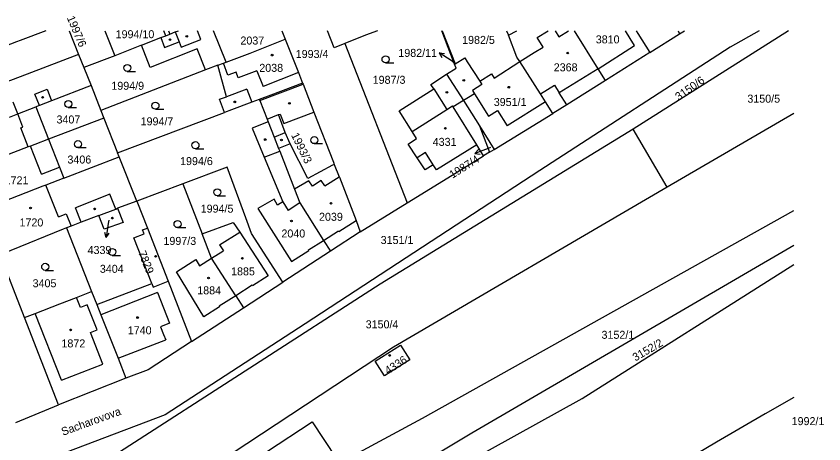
# Model space of a CAD drawing. Extents: x -564952 to -564307, y -1202373 to -1201847.
# Drawn here: x -564479.9 to -564308.3, y -1201937.9 to -1201847 of the extents above; entities that cross this region are included whole.
import ezdxf

# ---------------------------------------------------------------- set-up
doc = ezdxf.new("R2010")
doc.units = 0
for name, color, linetype in [('Hranice parcel', 7, 'Continuous'), ('Parcelní čísla', 7, 'Continuous'), ('Pop  PČ popisy', 7, 'Continuous'), ('Vnitřní kresba', 7, 'Continuous'), ('Značky budov', 7, 'Continuous'), ('Značky kultur', 7, 'Continuous')]:
    doc.layers.add(name, color=color, linetype=linetype)

msp = doc.modelspace()

# ---------------------------------------------------------------- linework, layer by layer
at = {"layer": 'Hranice parcel'}
for p, q in [((-564468.61, -1201850.07), (-564466.6, -1201855.11)), ((-564461.02, -1201850.07), (-564458.94, -1201855.38)), ((-564448.11, -1201851.13), (-564448.52, -1201850.07)), ((-564448.11, -1201851.13), (-564447.23, -1201850.78)), ((-564412.32, -1201853.69), (-564413.74, -1201850.07)), ((-564386.74, -1201857.21), (-564389.41, -1201850.07)), ((-564389.34, -1201850.07), (-564386.6, -1201857.12)), ((-564375.67, -1201850.07), (-564375.3, -1201851.01)), ((-564375.3, -1201851.01), (-564373.49, -1201850.07)), ((-564315.76, -1201850.07), (-564348.82, -1201871.01)), ((-564345.27, -1201854.72), (-564338.97, -1201850.76)), ((-564339.24, -1201850.07), (-564338.97, -1201850.76)), ((-564338.97, -1201850.76), (-564337.86, -1201850.07)), ((-564322.01, -1201850.07), (-564328.21, -1201853.59)), ((-564453.25, -1201853.14), (-564458.94, -1201855.38)), ((-564430.18, -1201854.86), (-564422.73, -1201851.85)), ((-564410.05, -1201852.79), (-564412.32, -1201853.69)), ((-564410.05, -1201852.79), (-564396.77, -1201886.65)), ((-564345.27, -1201854.72), (-564354.7, -1201860.63)), ((-564466.6, -1201855.11), (-564477.53, -1201859.28)), ((-564466.6, -1201855.11), (-564465.47, -1201857.93)), ((-564458.94, -1201855.38), (-564465.47, -1201857.93)), ((-564465.47, -1201857.93), (-564463.95, -1201861.74)), ((-564437.04, -1201857.43), (-564439.67, -1201858.41)), ((-564386.6, -1201857.12), (-564386.74, -1201857.21)), ((-564354.7, -1201860.63), (-564356.22, -1201858.17)), ((-564439.67, -1201858.41), (-564461.87, -1201867.04)), ((-564463.95, -1201861.74), (-564461.87, -1201867.04)), ((-564474.94, -1201865.99), (-564475.71, -1201866.29)), ((-564475.71, -1201866.29), (-564473.01, -1201873.15)), ((-564461.24, -1201868.64), (-564473.01, -1201873.15)), ((-564461.87, -1201867.04), (-564461.24, -1201868.64)), ((-564461.24, -1201868.64), (-564458.32, -1201876.01)), ((-564458.32, -1201876.01), (-564435.59, -1201867.46)), ((-564378.3, -1201875.31), (-564365.83, -1201867.67)), ((-564314.65, -1201867.64), (-564341.58, -1201883.31)), ((-564381.45, -1201870.33), (-564378.3, -1201875.31)), ((-564381.45, -1201870.33), (-564379.28, -1201875.91)), ((-564341.58, -1201883.31), (-564348.82, -1201871.01)), ((-564379.28, -1201875.91), (-564378.3, -1201875.31)), ((-564469.76, -1201881.43), (-564457.98, -1201876.88)), ((-564457.98, -1201876.88), (-564458.32, -1201876.01)), ((-564454.24, -1201886.28), (-564457.98, -1201876.88)), ((-564379.28, -1201875.91), (-564380.57, -1201876.7)), ((-564435.05, -1201879.07), (-564444.43, -1201882.6)), ((-564444.43, -1201882.6), (-564454.24, -1201886.28)), ((-564444.43, -1201882.6), (-564440.35, -1201893.28)), ((-564454.24, -1201886.28), (-564458.32, -1201887.83)), ((-564454.24, -1201886.28), (-564452, -1201892.04)), ((-564406.77, -1201892.86), (-564396.77, -1201886.65)), ((-564469.2, -1201891.98), (-564463.85, -1201905.51)), ((-564452, -1201892.04), (-564447.6, -1201903.34)), ((-564438.38, -1201898.44), (-564440.35, -1201893.28)), ((-564423.2, -1201903.54), (-564429.86, -1201893.15)), ((-564406.77, -1201892.86), (-564413.1, -1201896.97)), ((-564414.61, -1201894.66), (-564413.1, -1201896.97)), ((-564478.1, -1201911.04), (-564483.28, -1201897.71)), ((-564413.1, -1201896.97), (-564423.2, -1201903.54)), ((-564440.95, -1201900.03), (-564438.38, -1201898.44)), ((-564433.23, -1201906.4), (-564438.38, -1201898.44)), ((-564462.75, -1201908.3), (-564451.07, -1201903.8)), ((-564447.6, -1201903.34), (-564442.6, -1201916.17)), ((-564431.61, -1201909.01), (-564423.2, -1201903.54)), ((-564463.85, -1201905.51), (-564462.75, -1201908.3)), ((-564433.23, -1201906.4), (-564431.61, -1201909.01)), ((-564475.84, -1201910.17), (-564470.62, -1201908.16)), ((-564442.6, -1201916.17), (-564431.61, -1201909.01)), ((-564478.1, -1201911.04), (-564475.84, -1201910.17)), ((-564470.88, -1201929.59), (-564478.1, -1201911.04)), ((-564456.57, -1201923.91), (-564470.88, -1201929.59)), ((-564479.94, -1201933.37), (-564470.88, -1201929.59))]:
    msp.add_line(p, q, dxfattribs=at)
for points in [[(-564473.57, -1201850.07), (-564479.02, -1201852.16), (-564479.81, -1201852.47)], [(-564453.25, -1201853.14), (-564449.16, -1201851.54), (-564448.11, -1201851.13)], [(-564447.23, -1201850.78), (-564446.06, -1201850.33), (-564445.4, -1201850.07)], [(-564423.43, -1201850.07), (-564422.73, -1201851.85)], [(-564403.1, -1201850.07), (-564405.63, -1201851.04), (-564410.05, -1201852.79)], [(-564372.86, -1201856.63), (-564373.48, -1201855.67), (-564375.3, -1201851.01)], [(-564356.22, -1201858.17), (-564361.26, -1201850.07)], [(-564348.14, -1201850.07), (-564347.77, -1201850.67), (-564345.27, -1201854.72)], [(-564479.81, -1201852.47), (-564485.57, -1201854.67), (-564486.52, -1201855.04)], [(-564439.67, -1201858.41), (-564441.45, -1201853.96), (-564451.37, -1201857.87), (-564453.25, -1201853.14)], [(-564422.73, -1201851.85), (-564419.92, -1201858.94), (-564419.02, -1201861.22)], [(-564328.21, -1201853.59), (-564368.6, -1201879.82), (-564418.44, -1201912.36), (-564448.23, -1201931.71), (-564529.16, -1201962.4)], [(-564437.04, -1201857.43), (-564435.86, -1201856.99), (-564435.27, -1201856.77), (-564430.18, -1201854.86)], [(-564386.6, -1201857.12), (-564384.58, -1201855.83), (-564384.05, -1201856.66), (-564381.38, -1201860.81), (-564378.92, -1201859.23), (-564378.35, -1201860.13), (-564372.86, -1201856.63)], [(-564365.83, -1201867.67), (-564367.43, -1201865.16), (-564368.48, -1201863.51), (-564372.86, -1201856.63)], [(-564435.59, -1201867.46), (-564436.64, -1201864.66), (-564435.18, -1201864.11), (-564437.04, -1201857.43)], [(-564388.42, -1201859.31), (-564386.43, -1201858.04), (-564386.74, -1201857.21)], [(-564477.53, -1201859.28), (-564481.06, -1201860.63), (-564482.46, -1201861.16), (-564484.41, -1201861.91)], [(-564380.57, -1201876.7), (-564382.03, -1201874.33), (-564390.55, -1201879.66), (-564391.25, -1201878.56), (-564392.97, -1201879.66), (-564394.68, -1201877.07), (-564396.59, -1201874.17), (-564394.79, -1201872.98), (-564395.72, -1201871.52), (-564398.51, -1201867.12), (-564391.16, -1201862.46), (-564391.79, -1201861.48), (-564388.42, -1201859.31)], [(-564388.42, -1201859.31), (-564384.87, -1201864.93), (-564381.45, -1201870.33)], [(-564463.95, -1201861.74), (-564472.34, -1201864.98), (-564474.94, -1201865.99)], [(-564419.02, -1201861.22), (-564425.76, -1201863.76), (-564428.23, -1201864.69)], [(-564419.02, -1201861.22), (-564418.92, -1201861.47), (-564416.62, -1201867.36)], [(-564354.7, -1201860.63), (-564362.91, -1201865.83), (-564365.83, -1201867.67)], [(-564428.23, -1201864.69), (-564429.82, -1201865.29), (-564434.13, -1201866.91), (-564435.59, -1201867.46)], [(-564428.23, -1201864.69), (-564428.13, -1201864.92), (-564426.58, -1201868.88), (-564426.35, -1201869.45)], [(-564481.3, -1201868.45), (-564479.53, -1201867.76), (-564475.71, -1201866.29)], [(-564412.28, -1201878.49), (-564412.7, -1201878.65), (-564417.92, -1201881.46), (-564421.69, -1201874.11), (-564422.7, -1201871.73), (-564424.14, -1201867.92), (-564423.81, -1201867.79), (-564423.04, -1201869.79), (-564416.62, -1201867.36)], [(-564416.62, -1201867.36), (-564412.46, -1201878.03), (-564412.28, -1201878.49)], [(-564426.35, -1201869.45), (-564429.75, -1201870.82), (-564427.19, -1201876.93), (-564423.21, -1201886.47), (-564424.37, -1201887.16), (-564425.08, -1201885.85), (-564428.5, -1201887.89), (-564421.37, -1201899.14), (-564417.7, -1201896.81), (-564417.78, -1201896.68), (-564414.61, -1201894.66)], [(-564426.35, -1201869.45), (-564425.09, -1201872.67), (-564424.13, -1201875.09), (-564423.89, -1201875.7), (-564420.71, -1201883.77), (-564419.58, -1201886.65), (-564414.61, -1201894.66)], [(-564348.82, -1201871.01), (-564402.54, -1201903.93), (-564457.9, -1201939.66)], [(-564473.01, -1201873.15), (-564475.91, -1201874.26), (-564476.86, -1201874.62), (-564477.31, -1201874.79), (-564488.03, -1201878.9), (-564490.31, -1201879.77)], [(-564473.01, -1201873.15), (-564470.67, -1201879.1), (-564469.76, -1201881.43)], [(-564396.77, -1201886.65), (-564392.78, -1201884.18), (-564380.57, -1201876.7)], [(-564412.28, -1201878.49), (-564411.25, -1201881.16), (-564411.21, -1201881.24), (-564407.64, -1201890.41), (-564406.77, -1201892.86)], [(-564429.86, -1201893.15), (-564431.08, -1201889.83), (-564435.05, -1201879.07)], [(-564469.76, -1201881.43), (-564473.58, -1201882.9), (-564474.18, -1201883.13)], [(-564474.18, -1201883.13), (-564484.77, -1201887.21), (-564487.03, -1201888.15)], [(-564341.58, -1201883.31), (-564399.74, -1201917.34), (-564446.42, -1201948.18)], [(-564458.32, -1201887.83), (-564457.17, -1201890.85), (-564461.2, -1201892.28), (-564462.31, -1201889.35)], [(-564462.31, -1201889.35), (-564458.72, -1201887.98), (-564458.32, -1201887.83)], [(-564428.74, -1201951.43), (-564393.56, -1201932.42), (-564314.65, -1201888.26)], [(-564462.31, -1201889.35), (-564466.09, -1201890.79), (-564468.22, -1201891.6), (-564469.2, -1201891.98)], [(-564440.35, -1201893.28), (-564433.75, -1201890.82), (-564432.39, -1201892.9)], [(-564469.2, -1201891.98), (-564469.88, -1201892.25), (-564480.99, -1201896.78), (-564483.28, -1201897.71)], [(-564451.07, -1201903.8), (-564454.85, -1201894.08), (-564452.68, -1201893.23), (-564453, -1201892.42), (-564452, -1201892.04)], [(-564432.39, -1201892.9), (-564426.32, -1201902.19), (-564429.69, -1201904.33), (-564429.77, -1201904.2), (-564433.23, -1201906.4)], [(-564383.08, -1201935.53), (-564314.65, -1201895.68)], [(-564433.23, -1201906.4), (-564436.77, -1201908.65), (-564436.69, -1201908.77), (-564440.03, -1201910.89), (-564445.78, -1201901.35), (-564441.69, -1201898.72), (-564440.95, -1201900.03)], [(-564359.6, -1201928.27), (-564314.65, -1201899.76)], [(-564451.07, -1201903.8), (-564450.77, -1201904.57), (-564447.6, -1201903.34)], [(-564470.62, -1201908.16), (-564467.08, -1201906.76), (-564463.85, -1201905.51)], [(-564462.75, -1201908.3), (-564461.88, -1201910.49), (-564458.23, -1201919.71), (-564456.57, -1201923.91)], [(-564442.6, -1201916.17), (-564451.86, -1201922.16), (-564456.57, -1201923.91)], [(-564401.64, -1201923.47), (-564403.6, -1201920.35), (-564398.19, -1201916.95), (-564396.24, -1201920.07), (-564401.64, -1201923.47)], [(-564479.51, -1201991.57), (-564446.91, -1201976.65), (-564359.6, -1201928.27)], [(-564314.65, -1201928.08), (-564320.77, -1201931.52), (-564331.09, -1201937.56), (-564341.36, -1201943.65), (-564351.71, -1201949.82)], [(-564426.66, -1201939.6), (-564416.96, -1201933.2), (-564411.87, -1201940.91), (-564421.6, -1201947.33), (-564426.66, -1201939.6)], [(-564479.51, -1201991.57), (-564464.1, -1201982.45), (-564434.29, -1201966.3), (-564383.08, -1201935.53)]]:
    msp.add_lwpolyline(points, dxfattribs=at)
at = {"layer": 'Pop  PČ popisy'}
for p, q in [((-564387.49, -1201856.44), (-564390.01, -1201854.81)), ((-564390.01, -1201854.81), (-564388.89, -1201854.93)), ((-564390.01, -1201854.81), (-564389.44, -1201855.77)), ((-564386.81, -1201856.89), (-564387.49, -1201856.44)), ((-564379.62, -1201875.11), (-564382.42, -1201876.19)), ((-564382.42, -1201876.19), (-564381.67, -1201875.36)), ((-564379.07, -1201874.9), (-564379.62, -1201875.11)), ((-564382.42, -1201876.19), (-564381.31, -1201876.29)), ((-564460.2, -1201890.32), (-564460.3, -1201891.07)), ((-564460.3, -1201891.07), (-564460.72, -1201894.04)), ((-564460.72, -1201894.04), (-564461.07, -1201892.98)), ((-564460.72, -1201894.04), (-564460.08, -1201893.12))]:
    msp.add_line(p, q, dxfattribs=at)
at = {"layer": 'Vnitřní kresba'}
for p, q in [((-564447.51, -1201850.07), (-564447.23, -1201850.78)), ((-564446.06, -1201850.33), (-564445.24, -1201852.42)), ((-564440.62, -1201851.96), (-564441.36, -1201850.07)), ((-564435.27, -1201856.77), (-564437.94, -1201850.07)), ((-564369.2, -1201851.52), (-564366.88, -1201850.07)), ((-564365.37, -1201850.07), (-564364.58, -1201851.34)), ((-564364.58, -1201851.34), (-564362.53, -1201850.07)), ((-564349.43, -1201851.7), (-564350.44, -1201850.07)), ((-564449.16, -1201851.54), (-564448.35, -1201853.63)), ((-564448.35, -1201853.63), (-564445.24, -1201852.42)), ((-564445.24, -1201852.42), (-564444.79, -1201853.59)), ((-564444.79, -1201853.59), (-564440.62, -1201851.96)), ((-564367.94, -1201853.55), (-564369.2, -1201851.52)), ((-564348.5, -1201853.22), (-564349.43, -1201851.7)), ((-564372.86, -1201856.63), (-564369.82, -1201854.73)), ((-564369.82, -1201854.73), (-564367.94, -1201853.55)), ((-564356.22, -1201858.17), (-564348.5, -1201853.22)), ((-564434.91, -1201859.54), (-564435.86, -1201856.99)), ((-564356.22, -1201858.17), (-564364.48, -1201863.31)), ((-564433.16, -1201858.89), (-564434.91, -1201859.54)), ((-564432.7, -1201860.1), (-564433.16, -1201858.89)), ((-564428.71, -1201858.62), (-564432.7, -1201860.1)), ((-564428.71, -1201858.62), (-564427.42, -1201861.91)), ((-564419.92, -1201858.94), (-564427.42, -1201861.91)), ((-564428.13, -1201864.92), (-564418.92, -1201861.47)), ((-564380.92, -1201861.53), (-564382.95, -1201862.8)), ((-564381.38, -1201860.81), (-564380.92, -1201861.53)), ((-564368.48, -1201863.51), (-564365.51, -1201861.66)), ((-564365.51, -1201861.66), (-564364.48, -1201863.31)), ((-564475.89, -1201863.53), (-564473.31, -1201862.48)), ((-564473.31, -1201862.48), (-564472.34, -1201864.98)), ((-564430.88, -1201862.48), (-564435.18, -1201864.11)), ((-564430.88, -1201862.48), (-564429.82, -1201865.29)), ((-564391.16, -1201862.46), (-564388.38, -1201866.82)), ((-564382.52, -1201863.48), (-564383.81, -1201864.28)), ((-564382.95, -1201862.8), (-564382.52, -1201863.48)), ((-564382.52, -1201863.48), (-564379.54, -1201868.23)), ((-564362.91, -1201865.83), (-564364.48, -1201863.31)), ((-564474.94, -1201865.99), (-564475.89, -1201863.53)), ((-564384.87, -1201864.93), (-564387.02, -1201866.26)), ((-564383.81, -1201864.28), (-564384.87, -1201864.93)), ((-564367.43, -1201865.16), (-564375.55, -1201870.26)), ((-564479.53, -1201867.76), (-564480.49, -1201865.23)), ((-564395.72, -1201871.52), (-564388.38, -1201866.82)), ((-564388.38, -1201866.82), (-564387.16, -1201866.04)), ((-564387.02, -1201866.26), (-564387.16, -1201866.04)), ((-564382.03, -1201874.33), (-564387.02, -1201866.26)), ((-564478.47, -1201870.56), (-564479.53, -1201867.76)), ((-564426.58, -1201868.88), (-564424.14, -1201867.92)), ((-564379.54, -1201868.23), (-564377.59, -1201867.01)), ((-564377.59, -1201867.01), (-564375.55, -1201870.26)), ((-564478.86, -1201870.71), (-564478.47, -1201870.56)), ((-564477.31, -1201874.79), (-564478.86, -1201870.71)), ((-564425.09, -1201872.67), (-564422.7, -1201871.73)), ((-564474.49, -1201880.6), (-564476.86, -1201874.62)), ((-564421.69, -1201874.11), (-564424.13, -1201875.09)), ((-564427.19, -1201876.93), (-564423.89, -1201875.7)), ((-564392.91, -1201875.95), (-564394.68, -1201877.07)), ((-564391.25, -1201878.56), (-564392.91, -1201875.95)), ((-564474.49, -1201880.6), (-564470.67, -1201879.1)), ((-564417.72, -1201882.01), (-564420.71, -1201883.77)), ((-564416.94, -1201883.12), (-564417.72, -1201882.01)), ((-564415.06, -1201881.91), (-564416.94, -1201883.12)), ((-564414.3, -1201883.03), (-564415.06, -1201881.91)), ((-564414.3, -1201883.03), (-564411.25, -1201881.16)), ((-564470.91, -1201889.66), (-564473.58, -1201882.9)), ((-564459.96, -1201884.82), (-564467.3, -1201887.7)), ((-564458.72, -1201887.98), (-564459.96, -1201884.82)), ((-564423.21, -1201886.47), (-564422.1, -1201888.27)), ((-564419.58, -1201886.65), (-564422.1, -1201888.27)), ((-564470.91, -1201889.66), (-564469.27, -1201889.02)), ((-564469.27, -1201889.02), (-564468.22, -1201891.6)), ((-564466.09, -1201890.79), (-564467.3, -1201887.7)), ((-564411.33, -1201892.76), (-564407.64, -1201890.41)), ((-564414.61, -1201894.66), (-564411.41, -1201892.63)), ((-564411.41, -1201892.63), (-564411.33, -1201892.76)), ((-564436.64, -1201895.58), (-564432.39, -1201892.9)), ((-564436.64, -1201895.58), (-564435.82, -1201896.86)), ((-564438.38, -1201898.44), (-564435.99, -1201896.96)), ((-564435.99, -1201896.96), (-564435.82, -1201896.86)), ((-564449.85, -1201905.73), (-564461.88, -1201910.49)), ((-564449.85, -1201905.73), (-564447.32, -1201912.27)), ((-564466.21, -1201908.95), (-564467.08, -1201906.76)), ((-564464.77, -1201908.37), (-564466.21, -1201908.95)), ((-564462.66, -1201913.67), (-564464.77, -1201908.37)), ((-564470.26, -1201924.35), (-564475.84, -1201910.17)), ((-564447.32, -1201912.27), (-564449.18, -1201912.99)), ((-564449.18, -1201912.99), (-564448.54, -1201914.66)), ((-564464.1, -1201914.24), (-564462.66, -1201913.67)), ((-564461.43, -1201920.98), (-564464.1, -1201914.24)), ((-564448.54, -1201914.66), (-564448.1, -1201915.79)), ((-564458.23, -1201919.71), (-564448.1, -1201915.79)), ((-564470.26, -1201924.35), (-564461.43, -1201920.98))]:
    msp.add_line(p, q, dxfattribs=at)
at = {"layer": 'Značky budov'}
for centre in [(-564443.62, -1201851.26), (-564447.2, -1201851.97), (-564362.7, -1201854.82), (-564425.49, -1201855.26), (-564384.77, -1201860.63), (-564388.37, -1201863.16), (-564375.22, -1201862.09), (-564474.25, -1201864.24), (-564433.42, -1201865.21), (-564421.82, -1201865.5), (-564388.69, -1201870.82), (-564426.97, -1201873.21), (-564423.52, -1201873.3), (-564412.98, -1201886.76), (-564476.81, -1201887.76), (-564463.2, -1201887.95), (-564459.44, -1201889.91), (-564421.39, -1201890.51), (-564450.24, -1201898.04), (-564431.81, -1201898.45), (-564439, -1201902.65), (-564454.08, -1201911.05), (-564468.31, -1201913.67), (-564400.51, -1201919.11)]:
    msp.add_circle(centre, 0.175, dxfattribs=at)
at = {"layer": 'Značky kultur'}
for p, q in [((-564401.4, -1201856.91), (-564399.65, -1201856.91)), ((-564456.26, -1201858.74), (-564454.51, -1201858.74)), ((-564468.79, -1201866.4), (-564467.04, -1201866.4)), ((-564450.28, -1201866.76), (-564448.53, -1201866.76)), ((-564466.74, -1201874.93), (-564464.99, -1201874.93)), ((-564441.78, -1201875.16), (-564440.03, -1201875.16)), ((-564416.53, -1201874.08), (-564414.78, -1201874.08)), ((-564437.14, -1201885.17), (-564435.39, -1201885.17)), ((-564445.59, -1201891.94), (-564443.84, -1201891.94)), ((-564459.47, -1201897.85), (-564457.72, -1201897.85)), ((-564473.7, -1201901.02), (-564471.95, -1201901.02))]:
    msp.add_line(p, q, dxfattribs=at)
for centre in [(-564401.4, -1201856.16), (-564456.26, -1201857.99), (-564468.79, -1201865.65), (-564450.28, -1201866.01), (-564466.74, -1201874.18), (-564441.78, -1201874.41), (-564416.53, -1201873.33), (-564437.14, -1201884.42), (-564445.59, -1201891.19), (-564459.47, -1201897.1), (-564473.7, -1201900.27)]:
    msp.add_circle(centre, 0.75, dxfattribs=at)

# ---------------------------------------------------------------- texts
at = {"layer": 'Parcelní čísla'}
for s, rotation, p in [('1997/6', 293, (-564469.14, -1201847.33)), ('3150/6', 35, (-564339.13, -1201864.99)), ('1993/3', 296, (-564421.51, -1201872.26)), ('1987/4', 32, (-564387.19, -1201881.56)), ('7829', 292, (-564453.99, -1201897.25)), ('3152/2', 30, (-564348.32, -1201920.41)), ('4336', 33, (-564400.89, -1201923.21))]:
    msp.add_text(s, height=1.7, rotation=rotation, dxfattribs=at).set_placement(p)
for s, p in [('1994/10', (-564458.74, -1201851.67)), ('2037', (-564432.23, -1201853.01)), ('1982/5', (-564385.13, -1201852.88)), ('3810', (-564356.74, -1201852.77)), ('1993/4', (-564420.48, -1201855.87)), ('1982/11', (-564398.68, -1201855.64)), ('2038', (-564428.22, -1201858.82)), ('2368', (-564365.67, -1201858.71)), ('1987/3', (-564404.13, -1201861.36)), ('1994/9', (-564459.65, -1201862.63)), ('3951/1', (-564378.41, -1201866.08)), ('3150/5', (-564324.53, -1201865.37)), ('3407', (-564471.3, -1201869.79)), ('1994/7', (-564453.43, -1201870.19)), ('4331', (-564391.38, -1201874.55)), ('3406', (-564468.98, -1201878.31)), ('1994/6', (-564445.05, -1201878.64)), ('1721', (-564482.32, -1201882.73)), ('1994/5', (-564440.67, -1201888.75)), ('2039', (-564415.53, -1201890.48)), ('1720', (-564479.16, -1201891.68)), ('2040', (-564423.52, -1201894.03)), ('1997/3', (-564448.58, -1201895.61)), ('3151/1', (-564402.44, -1201895.42)), ('4339', (-564464.7, -1201897.55)), ('3404', (-564462.09, -1201901.54)), ('1885', (-564434.21, -1201902.08)), ('3405', (-564476.38, -1201904.61)), ('1884', (-564441.4, -1201906.12)), ('1740', (-564456.16, -1201914.61)), ('3150/4', (-564405.62, -1201913.34)), ('3152/1', (-564355.51, -1201915.57)), ('1872', (-564470.25, -1201917.4)), ('1992/1', (-564315.12, -1201933.92))]:
    msp.add_text(s, height=1.7, dxfattribs=at).set_placement(p)
at = {"layer": 'Pop  PČ popisy'}
msp.add_text('Sacharovova', height=1.7, rotation=20, dxfattribs=at).set_placement((-564469.91, -1201936.19))

doc.saveas('drawing.dxf')
